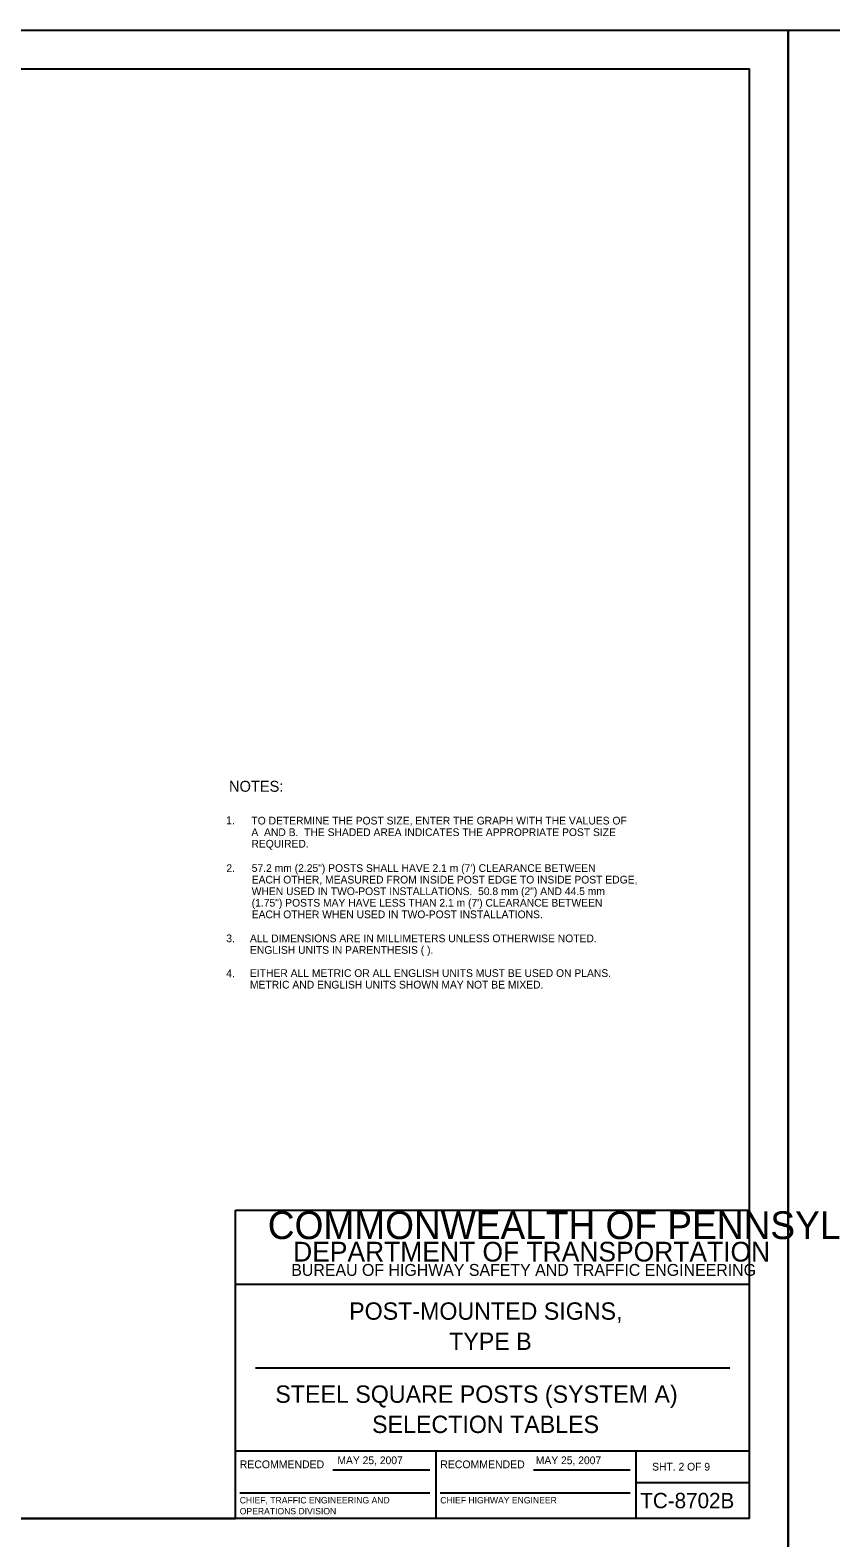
# Model space of a CAD drawing. Extents: x 644358 to 648627, y 294594 to 295782.
# Drawn here: x 645745 to 646057, y 295195 to 295782 of the extents above; entities that cross this region are included whole.
import ezdxf

# ---------------------------------------------------------------- set-up
doc = ezdxf.new("R2010")
doc.units = 0
for name, color, linetype in [('1', 7, 'Continuous'), ('2', 7, 'Continuous'), ('4', 7, 'Continuous'), ('PLT-BNDY', 7, 'Continuous')]:
    doc.layers.add(name, color=color, linetype=linetype)

msp = doc.modelspace()

# ---------------------------------------------------------------- linework, layer by layer
at = {"layer": '1'}
for p, q in [((645239.31, 295766.63), (646025.31, 295766.63)), ((646025.31, 295202.63), (646025.31, 295766.63)), ((645825.31, 295202.63), (645825.31, 295322.63)), ((645825.31, 295322.63), (646025.31, 295322.63)), ((646025.31, 295293.63), (645825.31, 295293.63)), ((645833.06, 295261.31), (646017.56, 295261.31)), ((645825.31, 295229), (646025.31, 295229)), ((645903.31, 295229), (645903.31, 295202.63)), ((645981.19, 295202.63), (645981.19, 295229)), ((645863.24, 295221.57), (645900.87, 295221.57)), ((645941.24, 295221.57), (645978.87, 295221.57)), ((645981.19, 295216.63), (646025.31, 295216.63)), ((645826.99, 295212.68), (645900.87, 295212.68)), ((645904.99, 295212.68), (645978.87, 295212.68)), ((646025.31, 295202.63), (645239.31, 295202.63)), ((645239.31, 295202.63), (645825.31, 295202.63))]:
    msp.add_line(p, q, dxfattribs=at)
at = {"layer": 'PLT-BNDY'}
for points in [[(645199.31, 295781.63), (646040.31, 295781.63), (646040.31, 295187.63), (645199.31, 295187.63)], [(646040.31, 295781.63), (646881.31, 295781.63), (646881.31, 295187.63), (646040.31, 295187.63)]]:
    msp.add_lwpolyline(points, close=True, dxfattribs=at)

# ---------------------------------------------------------------- texts
at = {"layer": '1'}
for s, height, p in [('1. ', 3.089, (645821.66, 295472.72)), ('2. ', 3, (645821.79, 295454.14)), ('3. ', 3, (645821.75, 295426.84)), ('4. ', 3, (645821.74, 295413.22)), ('COMMONWEALTH OF PENNSYLVANIA', 10.7828, (645837.9, 295311.36)), ('DEPARTMENT OF TRANSPORTATION', 7.6837, (645847.76, 295302.61)), ('BUREAU OF HIGHWAY SAFETY AND TRAFFIC ENGINEERING', 4.6253, (645847.04, 295297.04)), ('POST-MOUNTED SIGNS,', 6.75, (645869.54, 295279.97)), ('TYPE B', 6.75, (645908.45, 295268.22)), ('STEEL SQUARE POSTS (SYSTEM A)', 6.75, (645840.84, 295247.66)), ('SELECTION TABLES', 6.75, (645878.47, 295235.91)), ('RECOMMENDED', 3.048, (645826.99, 295222.2)), ('RECOMMENDED', 3.048, (645904.99, 295222.2)), ('SHT. 2 OF 9', 3, (645987.39, 295221.31)), ('CHIEF, TRAFFIC ENGINEERING AND', 2.5, (645826.99, 295208.51)), ('CHIEF HIGHWAY ENGINEER', 2.5, (645904.99, 295208.51)), ('TC-8702B', 6, (645982.77, 295206.63)), ('OPERATIONS DIVISION', 2.5, (645826.99, 295204.26))]:
    msp.add_text(s, height=height, dxfattribs=at).set_placement(p)
at = {"layer": '2'}
for s, p in [('TO DETERMINE THE POST SIZE, ENTER THE GRAPH WITH THE VALUES OF ', (645831.53, 295472.63)), ('A  AND B.  THE SHADED AREA INDICATES THE APPROPRIATE POST SIZE ', (645831.53, 295468.13)), ('REQUIRED.', (645831.53, 295463.63)), ('57.2 mm (2.25") POSTS SHALL HAVE 2.1 m (7\') CLEARANCE BETWEEN', (645831.65, 295454.17)), ('EACH OTHER, MEASURED FROM INSIDE POST EDGE TO INSIDE POST EDGE,', (645831.65, 295449.67)), ('WHEN USED IN TWO-POST INSTALLATIONS.  50.8 mm (2") AND 44.5 mm', (645831.65, 295445.17)), ('(1.75") POSTS MAY HAVE LESS THAN 2.1 m (7\') CLEARANCE BETWEEN', (645831.65, 295440.67)), ('EACH OTHER WHEN USED IN TWO-POST INSTALLATIONS.', (645831.65, 295436.17)), ('ALL DIMENSIONS ARE IN MILLIMETERS UNLESS OTHERWISE NOTED.  ', (645830.97, 295426.82)), ('ENGLISH UNITS IN PARENTHESIS ( ).', (645830.97, 295422.32)), ('EITHER ALL METRIC OR ALL ENGLISH UNITS MUST BE USED ON PLANS.  ', (645830.97, 295413.32)), ('METRIC AND ENGLISH UNITS SHOWN MAY NOT BE MIXED.', (645830.97, 295408.82)), ('MAY 25, 2007', (645864.98, 295223.79)), ('MAY 25, 2007', (645942.14, 295223.79))]:
    msp.add_text(s, height=3, dxfattribs=at).set_placement(p)
at = {"layer": '4'}
msp.add_text('NOTES:', height=4.25, dxfattribs=at).set_placement((645822.82, 295485.36))

doc.saveas('drawing.dxf')
